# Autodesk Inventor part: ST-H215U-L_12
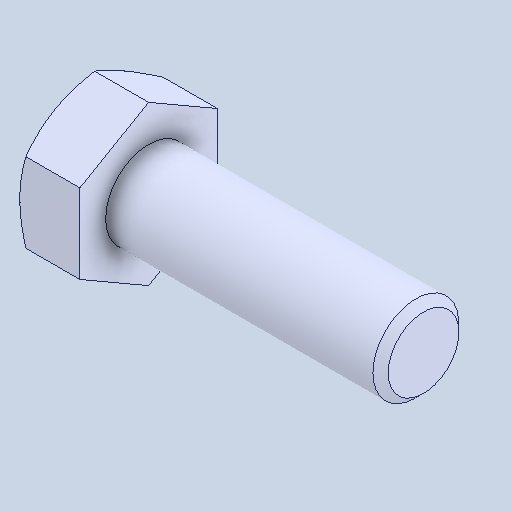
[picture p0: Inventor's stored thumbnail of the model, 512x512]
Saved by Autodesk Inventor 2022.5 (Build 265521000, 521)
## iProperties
Created: 2024-07
Part Number: ST-H215U-L_12
Material: 一般
Document SubType Name: Modeling
Designer: ImaoCorp
Density: 1 g/cm^3
Appearance: 既定
Author: ImaoCorp
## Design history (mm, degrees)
feature "ST-H215U-L_12"
node "ソリッド1"
